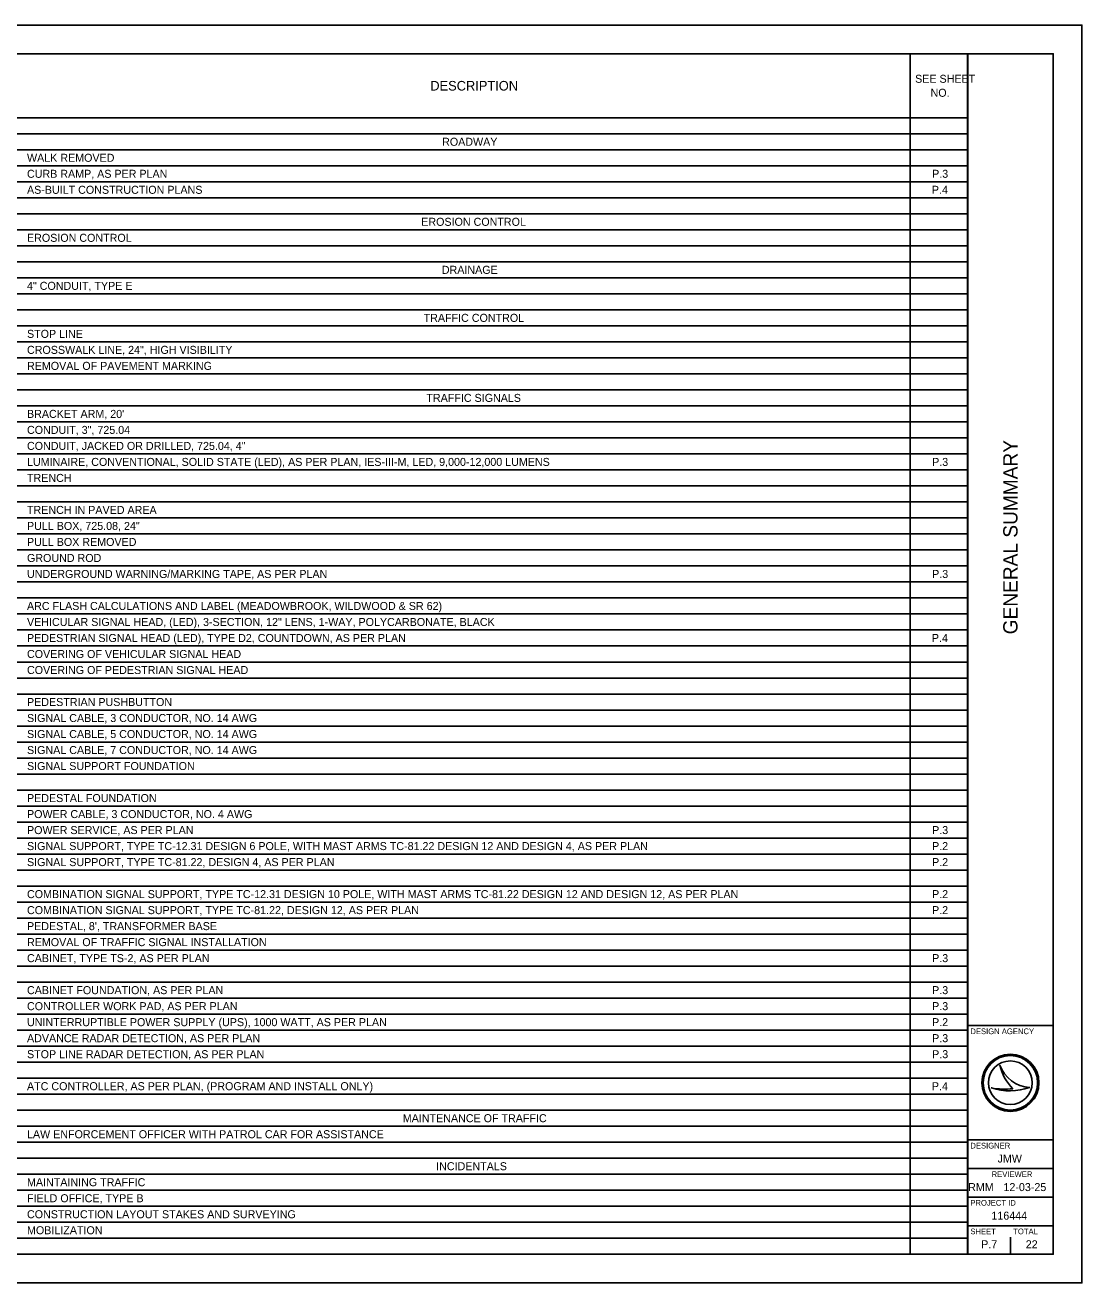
# Model space of a CAD drawing. Extents: x 0 to 34, y 0 to 22.
# Drawn here: x 15.52 to 34, y 0 to 22 of the extents above; entities that cross this region are included whole.
import ezdxf

# ---------------------------------------------------------------- set-up
doc = ezdxf.new("R2010")
doc.units = 0
for name, color, linetype in [('SH_Border', 7, 'Continuous'), ('SH_Cut_Line', 7, 'Continuous'), ('SH_Data', 7, 'Continuous'), ('SH_Text', 7, 'Continuous')]:
    doc.layers.add(name, color=color, linetype=linetype)

msp = doc.modelspace()

# ---------------------------------------------------------------- linework, layer by layer
at = {"layer": 'SH_Border'}
for p, q in [((32, 0.5), (32, 21.5)), ((32, 4.5), (33.5, 4.5)), ((32, 2.5), (33.5, 2.5)), ((32, 2), (33.5, 2)), ((32, 1.5), (33.5, 1.5)), ((32, 1), (33.5, 1))]:
    msp.add_line(p, q, dxfattribs=at)
msp.add_lwpolyline([(1.5, 21.5), (33.5, 21.5), (33.5, 0.5), (1.5, 0.5)], close=True, dxfattribs=at)
at = {"layer": 'SH_Cut_Line'}
msp.add_lwpolyline([(0, 0), (34, 0), (34, 22), (0, 22)], close=True, dxfattribs=at)
at = {"layer": 'SH_Data'}
for p, q in [((32.567, 3.81), (32.567, 3.81)), ((32.417, 3.41), (32.417, 3.41)), ((32.75, 3.5), (32.75, 3.5)), ((33.087, 3.419), (33.087, 3.419)), ((32.375, 0.675), (32.375, 0.675)), ((32.75, 0.5), (32.75, 0.8))]:
    msp.add_line(p, q, dxfattribs=at)
for radius in [0.5, 0.477, 0.477, 0.382]:
    msp.add_circle((32.75, 3.5), radius, dxfattribs=at)
for centre, radius, start, end in [((33.116, 3.998), 0.58, 198.9257, 198.9319), ((33.347, 3.97), 0.796, 191.6379, 191.6421), ((33.116, 3.998), 0.58, 198.9319, 267.1657), ((33.347, 3.97), 0.796, 191.6421, 226.0947), ((32.739, 4.37), 1.013, 251.4576, 290.0832), ((32.648, 4.654), 1.266, 259.4964, 259.4995), ((32.739, 4.37), 1.013, 251.4527, 251.4576), ((32.648, 4.654), 1.266, 259.4995, 276.6672)]:
    msp.add_arc(centre, radius, start, end, dxfattribs=at)
at = {"layer": 'SH_Text'}
for p, q in [((1.5, 21.5), (32.004, 21.5)), ((30.999, 21.5), (30.999, 0.5)), ((32.004, 21.5), (32.004, 0.5)), ((1.5, 20.38), (32.004, 20.38)), ((1.5, 20.1), (32.004, 20.1)), ((1.5, 19.82), (32.004, 19.82)), ((1.5, 19.54), (32.004, 19.54)), ((1.5, 19.26), (32.004, 19.26)), ((1.5, 18.98), (32.004, 18.98)), ((1.5, 18.7), (32.004, 18.7)), ((1.5, 18.42), (32.004, 18.42)), ((1.5, 18.14), (32.004, 18.14)), ((1.5, 17.86), (32.004, 17.86)), ((1.5, 17.58), (32.004, 17.58)), ((1.5, 17.3), (32.004, 17.3)), ((1.5, 17.02), (32.004, 17.02)), ((1.5, 16.74), (32.004, 16.74)), ((1.5, 16.46), (32.004, 16.46)), ((1.5, 16.18), (32.004, 16.18)), ((1.5, 15.9), (32.004, 15.9)), ((1.5, 15.62), (32.004, 15.62)), ((1.5, 15.34), (32.004, 15.34)), ((1.5, 15.06), (32.004, 15.06)), ((1.5, 14.78), (32.004, 14.78)), ((1.5, 14.5), (32.004, 14.5)), ((1.5, 14.22), (32.004, 14.22)), ((1.5, 13.94), (32.004, 13.94)), ((1.5, 13.66), (32.004, 13.66)), ((1.5, 13.38), (32.004, 13.38)), ((1.5, 13.1), (32.004, 13.1)), ((1.5, 12.82), (32.004, 12.82)), ((1.5, 12.54), (32.004, 12.54)), ((1.5, 12.26), (32.004, 12.26)), ((1.5, 11.98), (32.004, 11.98)), ((1.5, 11.7), (32.004, 11.7)), ((1.5, 11.42), (32.004, 11.42)), ((1.5, 11.14), (32.004, 11.14)), ((1.5, 10.86), (32.004, 10.86)), ((1.5, 10.58), (32.004, 10.58)), ((1.5, 10.3), (32.004, 10.3)), ((1.5, 10.02), (32.004, 10.02)), ((1.5, 9.74), (32.004, 9.74)), ((1.5, 9.46), (32.004, 9.46)), ((1.5, 9.18), (32.004, 9.18)), ((1.5, 8.9), (32.004, 8.9)), ((1.5, 8.62), (32.004, 8.62)), ((1.5, 8.34), (32.004, 8.34)), ((1.5, 8.06), (32.004, 8.06)), ((1.5, 7.78), (32.004, 7.78)), ((1.5, 7.5), (32.004, 7.5)), ((1.5, 7.22), (32.004, 7.22)), ((1.5, 6.94), (32.004, 6.94)), ((1.5, 6.66), (32.004, 6.66)), ((1.5, 6.38), (32.004, 6.38)), ((1.5, 6.1), (32.004, 6.1)), ((1.5, 5.82), (32.004, 5.82)), ((1.5, 5.54), (32.004, 5.54)), ((1.5, 5.26), (32.004, 5.26)), ((1.5, 4.98), (32.004, 4.98)), ((1.5, 4.7), (32.004, 4.7)), ((1.5, 4.42), (32.004, 4.42)), ((1.5, 4.14), (32.004, 4.14)), ((1.5, 3.86), (32.004, 3.86)), ((1.5, 3.58), (32.004, 3.58)), ((1.5, 3.3), (32.004, 3.3)), ((1.5, 3.02), (32.004, 3.02)), ((1.5, 2.74), (32.004, 2.74)), ((1.5, 2.46), (32.004, 2.46)), ((1.5, 2.18), (32.004, 2.18)), ((1.5, 1.9), (32.004, 1.9)), ((1.5, 1.62), (32.004, 1.62)), ((1.5, 1.34), (32.004, 1.34)), ((1.5, 1.06), (32.004, 1.06)), ((1.5, 0.78), (32.004, 0.78)), ((1.5, 0.5), (32.004, 0.5))]:
    msp.add_line(p, q, dxfattribs=at)

# ---------------------------------------------------------------- texts
at = {"layer": 'SH_Data'}
msp.add_text('GENERAL SUMMARY', height=0.25, rotation=90, dxfattribs=at).set_placement((32.875, 11.344))
for s, height, p in [('DESIGN AGENCY', 0.1, (32.05, 4.35)), ('DESIGNER', 0.1, (32.05, 2.35)), ('JMW', 0.14, (32.526, 2.105)), ('REVIEWER', 0.1, (32.422, 1.85)), ('RMM', 0.14, (32.011, 1.605)), ('12-03-25', 0.14, (32.629, 1.605)), ('PROJECT ID', 0.1, (32.05, 1.35)), ('116444', 0.14, (32.418, 1.105)), ('SHEET', 0.1, (32.05, 0.85)), ('TOTAL', 0.1, (32.8, 0.85)), ('P.7', 0.14, (32.239, 0.605)), ('22', 0.14, (33.019, 0.605))]:
    msp.add_text(s, height=height, dxfattribs=at).set_placement(p)
at = {"layer": 'SH_Text'}
for s, height, p in [('SEE SHEET ', 0.14, (31.084, 20.992)), ('DESCRIPTION', 0.168, (22.603, 20.856)), ('NO.', 0.14, (31.354, 20.747)), ('ROADWAY', 0.14, (22.81, 19.89)), ('WALK REMOVED', 0.14, (15.549, 19.61)), ('CURB RAMP, AS PER PLAN', 0.14, (15.549, 19.33)), ('P.3', 0.14, (31.381, 19.33)), ('AS-BUILT CONSTRUCTION PLANS', 0.14, (15.549, 19.05)), ('P.4', 0.14, (31.377, 19.05)), ('EROSION CONTROL', 0.14, (22.445, 18.49)), ('EROSION CONTROL', 0.14, (15.549, 18.21)), ('DRAINAGE', 0.14, (22.805, 17.65)), ('4" CONDUIT, TYPE E', 0.14, (15.549, 17.37)), ('TRAFFIC CONTROL', 0.14, (22.487, 16.81)), ('STOP LINE', 0.14, (15.549, 16.53)), ('CROSSWALK LINE, 24", HIGH VISIBILITY', 0.14, (15.549, 16.25)), ('REMOVAL OF PAVEMENT MARKING', 0.14, (15.549, 15.97)), ('TRAFFIC SIGNALS', 0.14, (22.535, 15.41)), ("BRACKET ARM, 20'", 0.14, (15.549, 15.13)), ('CONDUIT, 3", 725.04', 0.14, (15.549, 14.85)), ('CONDUIT, JACKED OR DRILLED, 725.04, 4"', 0.14, (15.549, 14.57)), ('LUMINAIRE, CONVENTIONAL, SOLID STATE (LED), AS PER PLAN, IES-III-M, LED, 9,000-12,000 LUMENS', 0.14, (15.549, 14.29)), ('P.3', 0.14, (31.381, 14.29)), ('TRENCH', 0.14, (15.549, 14.01)), ('TRENCH IN PAVED AREA', 0.14, (15.549, 13.45)), ('PULL BOX, 725.08, 24"', 0.14, (15.549, 13.17)), ('PULL BOX REMOVED', 0.14, (15.549, 12.89)), ('GROUND ROD', 0.14, (15.549, 12.61)), ('UNDERGROUND WARNING/MARKING TAPE, AS PER PLAN', 0.14, (15.549, 12.33)), ('P.3', 0.14, (31.381, 12.33)), ('ARC FLASH CALCULATIONS AND LABEL (MEADOWBROOK, WILDWOOD & SR 62)', 0.14, (15.549, 11.77)), ('VEHICULAR SIGNAL HEAD, (LED), 3-SECTION, 12" LENS, 1-WAY, POLYCARBONATE, BLACK', 0.14, (15.549, 11.49)), ('PEDESTRIAN SIGNAL HEAD (LED), TYPE D2, COUNTDOWN, AS PER PLAN', 0.14, (15.549, 11.21)), ('P.4', 0.14, (31.377, 11.21)), ('COVERING OF VEHICULAR SIGNAL HEAD', 0.14, (15.549, 10.93)), ('COVERING OF PEDESTRIAN SIGNAL HEAD', 0.14, (15.549, 10.65)), ('PEDESTRIAN PUSHBUTTON', 0.14, (15.549, 10.09)), ('SIGNAL CABLE, 3 CONDUCTOR, NO. 14 AWG', 0.14, (15.549, 9.81)), ('SIGNAL CABLE, 5 CONDUCTOR, NO. 14 AWG', 0.14, (15.549, 9.53)), ('SIGNAL CABLE, 7 CONDUCTOR, NO. 14 AWG', 0.14, (15.549, 9.25)), ('SIGNAL SUPPORT FOUNDATION', 0.14, (15.549, 8.97)), ('PEDESTAL FOUNDATION', 0.14, (15.549, 8.41)), ('POWER CABLE, 3 CONDUCTOR, NO. 4 AWG', 0.14, (15.549, 8.13)), ('POWER SERVICE, AS PER PLAN', 0.14, (15.549, 7.85)), ('P.3', 0.14, (31.381, 7.85)), ('SIGNAL SUPPORT, TYPE TC-12.31 DESIGN 6 POLE, WITH MAST ARMS TC-81.22 DESIGN 12 AND DESIGN 4, AS PER PLAN', 0.14, (15.549, 7.57)), ('P.2', 0.14, (31.38, 7.57)), ('SIGNAL SUPPORT, TYPE TC-81.22, DESIGN 4, AS PER PLAN', 0.14, (15.549, 7.29)), ('P.2', 0.14, (31.38, 7.29)), ('COMBINATION SIGNAL SUPPORT, TYPE TC-12.31 DESIGN 10 POLE, WITH MAST ARMS TC-81.22 DESIGN 12 AND DESIGN 12, AS PER PLAN', 0.14, (15.549, 6.73)), ('P.2', 0.14, (31.38, 6.73)), ('COMBINATION SIGNAL SUPPORT, TYPE TC-81.22, DESIGN 12, AS PER PLAN', 0.14, (15.549, 6.45)), ('P.2', 0.14, (31.38, 6.45)), ("PEDESTAL, 8', TRANSFORMER BASE", 0.14, (15.549, 6.17)), ('REMOVAL OF TRAFFIC SIGNAL INSTALLATION', 0.14, (15.549, 5.89)), ('CABINET, TYPE TS-2, AS PER PLAN', 0.14, (15.549, 5.61)), ('P.3', 0.14, (31.381, 5.61)), ('CABINET FOUNDATION, AS PER PLAN', 0.14, (15.549, 5.05)), ('P.3', 0.14, (31.381, 5.05)), ('CONTROLLER WORK PAD, AS PER PLAN', 0.14, (15.549, 4.77)), ('P.3', 0.14, (31.381, 4.77)), ('UNINTERRUPTIBLE POWER SUPPLY (UPS), 1000 WATT, AS PER PLAN', 0.14, (15.549, 4.49)), ('P.2', 0.14, (31.38, 4.49)), ('ADVANCE RADAR DETECTION, AS PER PLAN', 0.14, (15.549, 4.21)), ('P.3', 0.14, (31.381, 4.21)), ('STOP LINE RADAR DETECTION, AS PER PLAN', 0.14, (15.549, 3.93)), ('P.3', 0.14, (31.381, 3.93)), ('ATC CONTROLLER, AS PER PLAN, (PROGRAM AND INSTALL ONLY)', 0.14, (15.549, 3.37)), ('P.4', 0.14, (31.377, 3.37)), ('MAINTENANCE OF TRAFFIC', 0.14, (22.122, 2.81)), ('LAW ENFORCEMENT OFFICER WITH PATROL CAR FOR ASSISTANCE', 0.14, (15.549, 2.53)), ('INCIDENTALS', 0.14, (22.706, 1.97)), ('MAINTAINING TRAFFIC', 0.14, (15.549, 1.69)), ('FIELD OFFICE, TYPE B', 0.14, (15.549, 1.41)), ('CONSTRUCTION LAYOUT STAKES AND SURVEYING', 0.14, (15.549, 1.13)), ('MOBILIZATION', 0.14, (15.549, 0.85))]:
    msp.add_text(s, height=height, dxfattribs=at).set_placement(p)

doc.saveas('drawing.dxf')
